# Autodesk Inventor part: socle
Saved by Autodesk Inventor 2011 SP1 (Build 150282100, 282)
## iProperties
Created: 2010-12
Part Number: socle
Document SubType Name: Modeling
Designer: eric
Density: 1 g/cm^3
Author: eric
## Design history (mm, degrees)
feature "Base1"
node "Solide1"
node "Corps solides"
node "Corps surfaciques"
